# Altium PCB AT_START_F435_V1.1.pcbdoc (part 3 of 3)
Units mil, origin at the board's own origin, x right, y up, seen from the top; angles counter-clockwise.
Board outline 6521.81 x 4041.5 mil, 2 copper layers (Top Layer, Bottom Layer); 158 components, 212 nets, 714 pads, 868 vias.
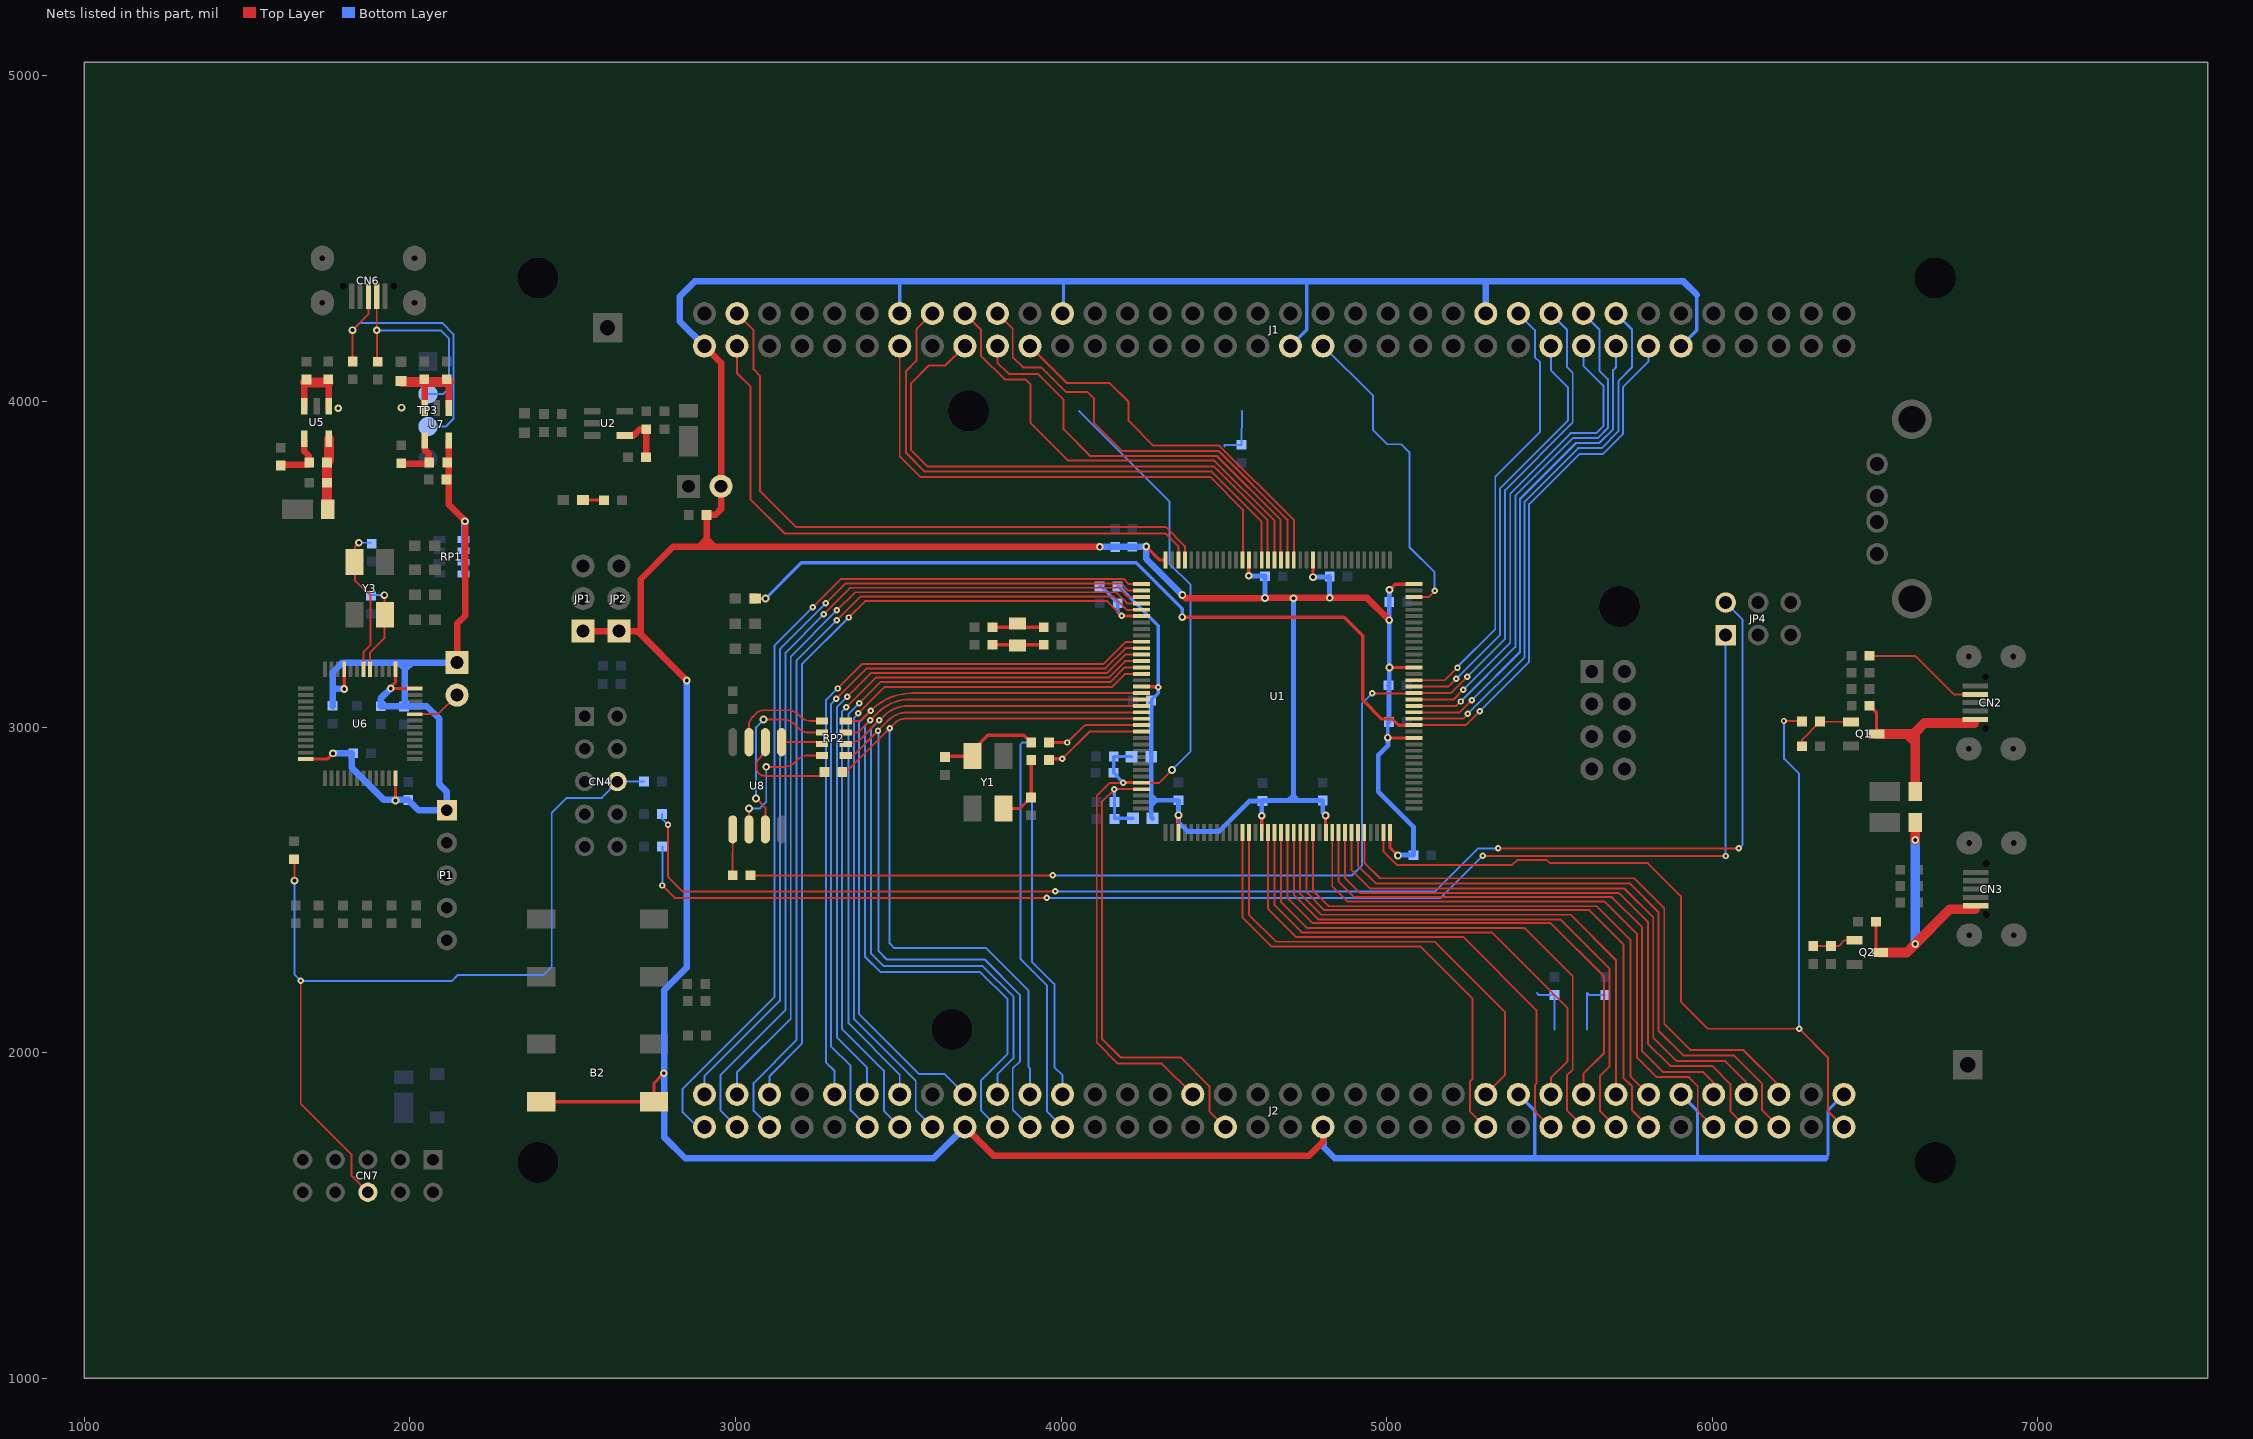
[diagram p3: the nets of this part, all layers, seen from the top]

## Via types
v1: diameter 19.69, hole 7.87, Top Layer to Bottom Layer, tented both sides, 787 vias
v2: diameter 23.62, hole 11.81, Top Layer to Bottom Layer, tented both sides, 53 vias
v3: diameter 24, hole 12, Top Layer to Bottom Layer, tented both sides, 17 vias
v4: diameter 35.43, hole 19.69, Top Layer to Bottom Layer, tented both sides, 11 vias

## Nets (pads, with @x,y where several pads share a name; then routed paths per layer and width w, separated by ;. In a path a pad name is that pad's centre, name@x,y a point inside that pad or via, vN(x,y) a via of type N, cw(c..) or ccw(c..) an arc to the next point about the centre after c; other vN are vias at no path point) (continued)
PD15: J1.14 LED4.2 U1.86 | length 4029.4
  Top Layer w6: U1.86@5084,3005.78 5243.09,3005.76 v1(5285.64,3048.36) ; J1.14@5804.59,4145.06 J1.14@5804.59,4170.06
  Top Layer w10: LED4.2@3060.29,3394.86 v3@3092.49,3394.66 ; v2(4372.18,3337.49) 4869.39,3337.47 4926.59,3280.36 4926.59,3083.36 4985.59,3024.26 5017.99,3024.26 5036.49,3005.76 U1.86@5084,3005.78
  Bottom Layer w6: v1(5285.64,3048.36) 5437.69,3200.36 5437.69,3684.36 5591.69,3838.36 5663.69,3838.36 5726.19,3900.86 5726.19,4044.86 5804.59,4123.27 J1.14@5804.59,4170.06
  Bottom Layer w10: v3(3092.47,3394.62) 3202.41,3504.56 4230.69,3504.56 4372.19,3363.07 v2(4372.18,3337.49)
PE0: J1.69 U1.141 | length 1992.3
  Top Layer w6: J1.69@3004.59,4269.56 3055.69,4218.97 3055.69,4098.27 3075.89,4078.07 3075.89,3724.16 3185.69,3614.36 4321.59,3614.36 4380.19,3555.76 U1.141@4380.19,3512.57
PE1: J1.70 U1.142 | length 1904
  Top Layer w6: J1.70@3004.59,4169.56 3004.59,4087.36 3045.69,4046.26 3045.69,3700.26 3151.69,3594.36 4321.69,3594.36 4360.49,3555.57 U1.142@4360.49,3512.57
PE2: J2.1 U1.1 | length 2855.2
  Top Layer w6: v1(3237.64,3368.36) 3324.19,3454.86 4192.49,3454.86 4208.59,3438.86 U1.1@4247.29,3438.86
  Bottom Layer w6: J2.1@2904.61,1771.46 2882.59,1771.46 2837.69,1816.37 2837.69,1888.37 3119.29,2169.97 3119.29,3250.07 v1(3237.64,3368.36)
PE3: J2.2 U1.2 | length 2667.5
  Top Layer w6: v1(3277.64,3380.36) 3338.69,3441.47 4184.59,3441.47 4206.99,3419.16 U1.2@4247.29,3419.16
  Bottom Layer w6: J2.2@2904.59,1871.57 2904.59,1927.07 3136.59,2159.07 3136.59,3239.36 v1(3277.64,3380.36)
PE4: J2.3 U1.3 | length 2748.8
  Top Layer w6: v1(3271.64,3346.36) 3352.99,3427.76 4176.79,3427.76 4204.99,3399.47 U1.3@4247.29,3399.47
  Bottom Layer w6: J2.3@3004.61,1771.46 2953.69,1822.46 2953.69,1930.96 3153.69,2130.97 3153.69,3228.36 v1(3271.64,3346.36)
PE5: J2.4 U1.4 | length 2586.9
  Top Layer w6: v1(3311.64,3358.36) 3367.19,3413.97 4168.89,3413.97 4203.09,3379.76 U1.4@4247.29,3379.76
  Bottom Layer w6: J2.4@3004.61,1871.46 3004.59,1938.77 3169.69,2103.86 3169.69,3216.36 v1(3311.64,3358.36)
PE6: J2.5 U1.5 | length 2665.3
  Top Layer w6: v1(3311.64,3328.36) 3383.39,3400.16 4161.79,3400.16 4201.89,3360.07 U1.5@4247.29,3360.07
  Bottom Layer w6: J2.5@3104.59,1771.57 3055.39,1820.77 3055.39,1906.46 3187.69,2038.77 3187.69,3204.36 v1(3311.64,3328.36)
PE7: J2.58 U1.58 | length 1655.4
  Top Layer w6: U1.58@4734.59,2676.05 4734.59,2487.36 4798.69,2423.36 5565.19,2423.36 5704.59,2283.97 J2.58@5704.61,1871.46
PE8: J2.59 U1.59 | length 1816.5
  Top Layer w6: U1.59@4754.19,2676.07 4754.19,2491.76 4808.69,2437.36 5622.59,2437.36 5727.19,2332.76 5727.19,1922.57 5753.69,1896.07 5753.69,1822.46 J2.59@5804.61,1771.46
PE9: J2.60 U1.60 | length 1714.1
  Top Layer w6: U1.60@4773.89,2676.07 4773.89,2497.07 4821.69,2449.36 5645.49,2449.36 5748.39,2346.47 5748.39,1927.66 J2.60@5804.61,1871.46
PE10: J2.63 U1.63 | length 1910
  Top Layer w6: U1.63@4833.01,2676.05 4832.99,2511.07 4879.69,2464.36 5668.89,2464.36 5768.49,2364.76 5768.49,1985.57 5829.69,1924.37 5928.39,1924.37 5955.69,1897.07 5955.69,1820.46 J2.63@6004.61,1771.46
PE11: J2.64 U1.64 | length 1817.7
  Top Layer w6: U1.64@4852.7,2676.05 4852.69,2525.26 4900.69,2477.36 5692.19,2477.36 5785.09,2384.47 5785.09,2003.46 5848.19,1940.37 5971.69,1940.37 6004.59,1907.37 J2.64@6004.61,1871.46
PE12: J2.65 U1.65 | length 1956.9
  Top Layer w6: U1.65@4872.29,2676.07 4872.29,2535.66 4917.69,2490.36 5713.49,2490.36 5802.39,2401.47 5802.39,2027.46 5870.49,1959.37 5999.69,1959.37 6055.69,1903.37 6055.69,1820.46 J2.65@6104.61,1771.46
PE13: J2.66 U1.66 | length 1851.3
  Top Layer w6: U1.66@4891.99,2676.07 4891.99,2560.97 4949.69,2503.36 5730.69,2503.36 5818.99,2415.07 5818.99,2045.57 5890.19,1974.37 6038.59,1974.37 6104.59,1908.37 J2.66@6104.61,1871.46
PE14: J2.67 U1.67 | length 1988.1
  Top Layer w6: U1.67@4911.75,2676.05 4911.69,2574.26 4966.69,2519.36 5746.99,2519.36 5835.09,2431.26 5835.09,2067.26 5911.99,1990.37 6067.19,1990.37 6153.69,1903.77 6153.69,1822.46 J2.67@6204.61,1771.46
PE15: J2.68 U1.68 | length 1884.7
  Top Layer w6: U1.68@4931.44,2676.05 4931.39,2583.57 4979.69,2535.36 5760.59,2535.36 5852.79,2443.16 5852.79,2088.16 5933.59,2007.37 6096.19,2007.37 6204.59,1898.96 J2.68@6204.61,1871.46
PF0: J2.10 U1.10 | length 2266
  Top Layer w6: v1@3313.69,3118.36 3388.99,3193.66 4130.99,3193.66 4198.99,3261.66 U1.10@4247.29,3261.66
  Bottom Layer w6: J2.10@3304.69,1871.46 3304.69,1943.37 3277.69,1970.27 3277.69,3082.36 v1@3313.69,3118.36
  other v1: 3313.64,3118.36
PF1: J2.11 U1.11 | length 2370.2
  Top Layer w6: v1@3309.69,3086.36 3403.19,3179.86 4136.19,3179.86 4198.29,3241.97 U1.11@4247.29,3241.97
  Bottom Layer w6: v1@3309.69,3086.36 3292.79,3069.47 3292.79,2019.77 3353.69,1958.87 3353.69,1822.46 J2.11@3404.59,1771.57
  other v1: 3309.64,3086.36
PF2: J2.12 U1.12 | length 2230
  Top Layer w6: v1@3343.69,3092.36 3417.39,3166.07 4141.39,3166.07 4197.59,3222.26 U1.12@4247.29,3222.26
  Bottom Layer w6: v1@3343.69,3092.36 3311.69,3060.36 3311.69,2046.96 3404.59,1954.07 J2.12@3404.61,1871.46
  other v1: 3343.64,3092.36
PF3: J2.13 U1.13 | length 2334.4
  Top Layer w6: v1@3339.69,3060.36 3431.19,3151.97 4145.99,3151.97 4196.69,3202.66 U1.13@4247.29,3202.66
  Bottom Layer w6: v1@3339.69,3060.36 3326.69,3047.36 3326.69,2073.36 3455.69,1944.27 3455.69,1820.57 J2.13@3504.59,1771.57
  other v1: 3339.64,3060.36
PF4: J2.14 U1.14 | length 2192.5
  Top Layer w6: v1@3379.69,3072.36 3445.09,3137.76 4150.99,3137.76 4196.19,3182.97 U1.14@4247.29,3182.97
  Bottom Layer w6: v1@3379.69,3072.36 3347.69,3040.36 3347.69,2089.36 3504.59,1932.46 J2.14@3504.59,1871.57
  other v1: 3379.64,3072.36
PF5: J2.15 U1.15 | length 2295.9
  Top Layer w6: v1(3377.64,3042.36) 3458.79,3123.57 4156.89,3123.57 4196.59,3163.26 U1.15@4247.29,3163.26
  Bottom Layer w6: v1(3377.64,3042.36) 3363.69,3027.57 3363.69,2103.36 3553.69,1913.37 3553.69,1822.46 J2.15@3604.61,1771.46
PF6: J2.18 RP2.4 U1.18 | length 2309.7
  Top Layer w6: RP2.4@3338.72,3018.67 cw(c3338.92,3018.47) 3338.92,3018.75 3375.79,3018.76 ; 3375.75,3018.75 ccw(c3375.75,3038.73) 3389.88,3024.6 v1(3415.64,3050.36) cw(c3545.62,2920.37) 3545.62,3104.19 ; 3545.59,3104.16 U1.18@4247.29,3104.16
  Bottom Layer w6: v1(3415.64,3050.36) 3379.69,3014.36 3379.69,2117.66 3562.89,1934.46 3641.69,1934.46 J2.18@3704.59,1871.57
PF7: J2.19 RP2.3 U1.19 | length 2615.1
  Top Layer w6: RP2.3@3338.72,2983.24 cw(c3338.85,2983.11) RP2.3@3338.85,2983.29 ; RP2.3@3338.89,2983.26 3371.39,2983.26 ; 3371.42,2983.29 ccw(c3371.42,2995.73) 3380.21,2986.93 v1(3413.64,3020.36) 3437.45,3044.17 cw(c3534.86,2946.76) 3534.86,3084.51 ; 3534.89,3084.57 U1.19@4247.29,3084.57
  Bottom Layer w6: v1@3413.69,3020.36 3397.69,3004.36 3397.69,2295.07 3445.49,2247.26 3751.59,2247.26 3835.59,2163.36 3835.59,1995.96 3753.69,1914.07 3753.69,1822.46 J2.19@3804.59,1771.57
PF8: J2.20 RP2.2 U1.20 | length 2489.2
  Top Layer w6: RP2.2@3338.72,2947.8 ccw(c3338.72,3021.09) 3390.55,2969.26 v1(3441.64,3020.36) 3454.97,3033.68 cw(c3530.2,2958.45) 3530.2,3064.85 3548.95,3064.85 cw(c3548.95,3064.77) 3549,3064.82 ; 3548.99,3064.86 U1.20@4247.29,3064.86
  Bottom Layer w6: v1(3441.64,3020.36) 3415.69,2994.36 3415.69,2305.47 3455.39,2265.76 3759.49,2265.76 3854.09,2171.26 3854.09,1983.37 3804.59,1933.87 J2.20@3804.61,1871.46
PF9: J2.21 RP2.1 U1.21 | length 2564.8
  Top Layer w6: RP2.1@3338.72,2912.37 3361.69,2912.36 v1@3437.69,2988.36 ; v1(3437.64,2988.36) 3471.06,3021.78 cw(c3527.47,2965.37) 3527.47,3045.14 ; 3527.49,3045.16 U1.21@4247.29,3045.16
  Bottom Layer w6: v1(3437.64,2988.36) 3439.69,2986.26 3439.69,2311.36 3465.19,2285.86 3764.99,2285.86 3874.19,2176.76 3874.19,1973.87 3851.69,1951.37 3851.69,1824.46 J2.21@3904.61,1771.46
PF10: J2.22 R21.1 U1.22 | length 2453.8
  Top Layer w6: R21.1@3328.05,2861.51 3338.89,2861.47 v1@3473.69,2996.36 ; v1(3473.64,2996.36) 3489.99,3012.71 cw(c3520.74,2981.95) 3520.75,3025.45 3543.87,3025.45 ; 3543.89,3025.47 U1.22@4247.29,3025.47
  Bottom Layer w6: v1@3473.69,2996.36 3473.69,2335.36 3488.09,2320.97 3769.79,2320.97 3899.79,2190.97 3899.79,1956.16 3904.89,1950.96 J2.22@3904.61,1871.46
PF11: J2.49 U1.49 | length 1489
  Top Layer w6: U1.49@4557.42,2676.05 4557.39,2414.57 4645.69,2326.36 5103.69,2326.36 5263.69,2166.36 5263.69,1918.37 5255.69,1910.37 5255.69,1820.46 J2.49@5304.61,1771.46
PF12: J2.50 U1.50 | length 1440.8
  Top Layer w6: U1.50@4577.11,2676.05 4577.09,2423.86 4660.59,2340.36 5147.79,2340.36 5364.29,2123.86 5364.29,1931.16 J2.50@5304.61,1871.46
PF13: J2.53 U1.53 | length 1569
  Top Layer w6: U1.53@4636.09,2676.07 4636.09,2440.36 4721.19,2355.36 5235.19,2355.36 5459.99,2130.57 5459.99,1904.66 5455.69,1900.37 5455.69,1820.46 J2.53@5504.61,1771.46
PF14: J2.54 U1.54 | length 1540.7
  Top Layer w6: U1.54@4655.85,2676.05 4655.79,2452.16 4738.69,2369.36 5322.79,2369.36 5555.69,2136.36 5555.69,1973.77 5504.59,1922.66 J2.54@5504.61,1871.46
PF15: J2.55 U1.55 | length 1695.3
  Top Layer w6: U1.55@4675.53,2676.05 4675.49,2463.26 4756.49,2382.36 5423.89,2382.36 5571.69,2234.57 5571.69,1947.66 5553.69,1929.66 5553.69,1822.46 J2.55@5604.61,1771.46
PG0: J2.56 U1.56 | length 1662.1
  Top Layer w6: U1.56@4695.22,2676.05 4695.19,2474.86 4772.69,2397.36 5504.19,2397.36 5667.69,2233.86 5667.69,1997.57 5604.59,1934.46 J2.56@5604.61,1871.46
PG1: J2.57 U1.57 | length 1774.5
  Top Layer w6: U1.57@4714.9,2676.05 4714.89,2484.07 4789.69,2409.36 5533.49,2409.36 5684.99,2257.86 5684.99,1957.66 5655.69,1928.37 5655.69,1820.46 J2.57@5704.61,1771.46
PG2: J1.15 U1.87 | length 1672.8
  Top Layer w6: U1.87@5084,3025.47 5234.69,3025.47 v1@5249.69,3040.36
  Bottom Layer w6: v1@5249.69,3040.36 5423.69,3214.36 5423.69,3692.36 5588.09,3856.76 5660.09,3856.76 5711.69,3908.36 5711.69,4062.36 5753.69,4104.36 5753.69,4220.97 J1.15@5704.59,4270.06
  other v1: 5249.64,3040.36
PG3: J1.16 U1.88 | length 1506.4
  Top Layer w6: U1.88@5084,3045.16 5224.39,3045.16 v1(5261.64,3082.36)
  Bottom Layer w6: v1(5261.64,3082.36) 5409.69,3230.36 5409.69,3700.36 5581.69,3872.36 5653.69,3872.36 5695.69,3914.36 5695.69,4096.47 5704.59,4105.36 J1.16@5704.59,4170.06
PG4: J1.17 U1.89 | length 1603.8
  Top Layer w6: U1.89@5083.99,3064.86 5214.09,3064.86 v1(5227.64,3078.36)
  Bottom Layer w6: v1(5227.64,3078.36) 5395.69,3246.36 5395.69,3710.36 5573.69,3888.36 5649.69,3888.36 5679.69,3918.36 5679.69,4068.36 5653.69,4094.36 5653.69,4220.97 J1.17@5604.59,4270.06
PG5: J1.18 U1.90 | length 1469.3
  Top Layer w6: U1.90@5084,3084.53 5205.79,3084.47 v1(5235.64,3114.36)
  Bottom Layer w6: v1(5235.64,3114.36) 5379.69,3258.36 5379.69,3716.97 5565.09,3902.36 5643.69,3902.36 5665.69,3924.36 5665.69,4048.36 5604.59,4109.36 J1.18@5604.59,4170.06
PG6: J1.19 R22.1 U1.91 | length 4023
  Top Layer w6: R22.1@3046.29,2544.37 v1@3974.69,2544.36 ; v1(4955.7,3103.45) 5083.29,3103.47 U1.91@5084,3104.2 5197.49,3104.16 v1(5247.64,3154.36)
  Bottom Layer w6: v1@3974.69,2544.36 4893.69,2544.36 4923.69,2574.36 4923.69,3071.45 v1(4955.7,3103.45) ; v1(5247.64,3154.36) 5363.69,3270.36 5363.69,3727.76 5571.69,3935.76 5571.69,4087.86 5553.69,4105.86 5553.69,4220.97 J1.19@5504.59,4270.06
  other v1: 3974.64,2544.36
PG7: J1.20 U1.92 | length 1326
  Top Layer w6: U1.92@5084,3123.89 5189.19,3123.86 v1@5213.69,3148.36
  Bottom Layer w6: v1@5213.69,3148.36 5347.69,3282.36 5347.69,3732.26 5557.69,3942.26 5557.69,4042.36 5504.59,4095.47 J1.20@5504.59,4170.06
  other v1: 5213.64,3148.36
PG8: J1.21 U1.93 | length 1370.4
  Top Layer w6: U1.93@5084,3143.57 5178.89,3143.57 v1(5217.64,3182.36)
  Bottom Layer w6: v1(5217.64,3182.36) 5217.64,3184.32 5333.69,3300.36 5333.69,3768.36 5471.69,3906.37 5471.69,4120.36 5455.69,4136.37 5455.69,4218.97 J1.21@5404.59,4270.06
PG9: J1.52 U1.124 | length 1212.9
  Top Layer w6: J1.52@3921.64,4153 J1.52@3904.61,4170.04 4018.29,4056.36 4149.59,4056.36 4207.69,3998.26 4207.69,3940.36 4283.69,3864.36 4486.59,3864.36 4714.89,3636.07 U1.124@4714.9,3512.68
PG10: J1.53 U1.125 | length 1371.6
  Top Layer w6: J1.53@3804.59,4270.06 3851.69,4222.97 3851.69,4136.36 3883.69,4104.36 3939.39,4104.36 4015.39,4028.36 4081.59,4028.36 4101.69,4008.36 4101.69,3933.57 4186.79,3848.36 4483.59,3848.36 4695.19,3636.76 U1.125@4695.22,3512.68
PG11: J1.54 U1.126 | length 1297.9
  Top Layer w6: J1.54@3804.59,4170.06 3804.59,4119.06 3839.29,4084.36 3927.89,4084.36 4007.69,4004.57 4007.69,3914.36 4089.69,3832.36 4478.69,3832.36 4674.69,3636.47 4674.69,3592.36 4674.69,3513.57 U1.126@4675.53,3512.68
PG12: J1.55 U1.127 | length 1451.3
  Top Layer w6: J1.55@3704.59,4270.06 3753.69,4220.97 3753.69,4140.36 3826.49,4067.57 3890.29,4067.57 3905.69,4052.16 3905.69,3935.16 4022.49,3818.36 4470.69,3818.36 4655.79,3633.16 U1.127@4655.85,3512.68
PG13: J1.56 U1.128 | length 1724.7
  Top Layer w6: J1.56@3704.59,4170.06 3644.89,4110.36 3593.69,4110.36 3539.69,4056.37 3539.69,3850.36 3589.7,3800.35 4468.73,3800.35 4634.64,3634.44 4634.64,3585.36 ; 4634.69,3585.36 4634.69,3514.16 U1.128@4636.09,3512.66
PG14: J1.57 U1.129 | length 1759.8
  Top Layer w6: J1.57@3604.59,4270.06 3555.69,4221.06 3555.69,4124.36 3523.69,4092.36 3523.69,3842.36 3581.69,3784.36 4463.09,3784.36 4615.59,3631.86 4615.59,3608.36 4615.59,3513.36 U1.129@4616.39,3512.66
PG15: J1.60 U1.132 | length 1616
  Top Layer w6: J1.60@3504.59,4170.06 3504.59,3831.37 3567.69,3768.36 4457.69,3768.36 4558.64,3667.41 4558.64,3595.36 ; U1.132@4557.42,3512.68 4558.69,3513.86 4558.69,3595.36
PH0/HEXT_IN: R1.2 U1.23 | length 430.5
  Top Layer w6: R1.2@3963.19,2952.36 v1(4019.64,2952.36) 4019.69,2952.36 4073.09,3005.76 U1.23@4247.29,3005.76
  Top Layer w10: R1.2@3963.14,2952.35 v1@4019.69,2952.36
  Bottom Layer w6: 3954.89,2952.36 v1@4019.69,2952.36 ; v1(4019.64,2952.36) v1@4021.65,2954.36
PH0_E: J2.23 | length 1265.6
  Bottom Layer w6: 3910.49,2952.36 3881.49,2952.36 3875.79,2946.66 3875.79,2287.26 3956.69,2206.36 3956.69,1819.46 J2.23@4004.61,1771.46
PH1/HEXT_OUT: R3.2 U1.24 | length 371.8
  Top Layer w6: v1@4003.69,2902.36 4087.39,2986.07 U1.24@4247.29,2986.07
  Top Layer w10: R3.2@3963.14,2898.35 3967.19,2902.36 v1@4003.69,2902.36
  Bottom Layer w6: 3954.89,2896.36 3960.89,2902.36 v1@4003.69,2902.36
  other v1: 4003.64,2902.36
PH1_E: J2.24 | length 1063.9
  Bottom Layer w6: 3910.49,2896.36 3910.49,2279.47 3979.79,2210.16 3979.79,1955.07 4004.59,1930.27 J2.24@4004.61,1871.46
PH2: J1.34 U1.106 | length 992.9
  Top Layer w6: U1.106@5084,3399.49 5130.79,3399.47 5147.59,3416.26 v1(5147.57,3418.26)
  Bottom Layer w6: J1.34@4804.59,4170.06 4805.99,4170.06 4957.69,4018.36 4957.69,3912.76 5001.89,3868.57 5045.59,3868.57 5069.69,3844.47 5069.69,3552.86 5147.59,3474.97 v1(5147.57,3418.26)
PH3: J2.71 R32.1 U1.71 | length 3141.6
  Top Layer w6: U1.71@4990.49,2676.05 4990.49,2617.47 5031.29,2576.66 5385.99,2576.66 5400.59,2591.26 5492.39,2591.26 5501.89,2581.76 5802.19,2581.76 5903.69,2480.26 5903.69,2155.47 5985.99,2073.16 6266.79,2073.16 6355.69,1984.27 6355.69,1820.46 J2.71@6404.61,1771.46 ; v1(6220.44,3018.36) 6274.19,3018.36 R32.1@6276,3016.56
  Bottom Layer w6: v1@6220.83,3017.96 6220.83,2902.12 6266.81,2856.14 v1(6266.81,2073.14)
Q1_1: Q1.1 R32.2 R33.1 | length 193.9
  Top Layer w6: R33.1@6276,2940.56 6275.99,2961.57 R32.2@6331,3016.56 Q1.1@6426.12,3015.97
QSPI1_IO0: RP2.7 U8.5 | length 126.6
  Top Layer w6: U8.5@3141.59,2953.36 3260.39,2953.36 RP2.7@3265.89,2947.8
QSPI1_IO1: RP2.8 U8.2 | length 416.2
  Top Layer w6: U8.2@3041.59,2685.66 3041.59,2750.07 v3@3042.39,2750.07 ; v3(3094.44,2877.7) 3150.84,2877.7 ccw(c3150.84,2919.4) 3180.33,2889.91 3189.41,2898.99 cw(c3221.7,2866.71) 3221.7,2912.37 RP2.8@3265.89,2912.37
  Bottom Layer w6: v3@3041.59,2750.07 3074.79,2750.07 3094.49,2769.76 v3@3094.49,2877.66
  other v3: 3041.55,2750.03
QSPI1_IO2: RP2.6 U8.3 | length 550.4
  Top Layer w6: v3(3063.31,2780.78) 3091.59,2752.57 U8.3@3091.59,2685.66 ; v3(3086.17,3022.68) 3146,3022.68 cw(c3146,2970.23) 3183.09,3007.32 3195.7,2994.71 ccw(c3223.27,3022.29) 3223.27,2983.29 ; 3223.29,2983.26 RP2.6@3265.79,2983.26 ; RP2.6@3265.76,2983.29 cw(c3265.76,2983.11) RP2.6@3265.89,2983.24
  Bottom Layer w6: v3(3063.31,2780.78) 3063.31,2999.83 v3(3086.17,3022.68)
QSPI1_IO3: RP2.5 U8.7 | length 310.8
  Top Layer w6: 3041.55,3004.66 cw(c3078.19,3004.66) 3052.28,3030.57 3064.25,3042.53 cw(c3085.77,3021.01) 3085.77,3051.45 3161.38,3051.45 cw(c3161.38,3005.71) 3193.72,3038.05 3201.05,3030.73 ccw(c3229.97,3059.65) 3229.97,3018.75 ; U8.7@3041.59,2953.36 3041.59,3004.66 ; 3229.99,3018.76 3265.69,3018.76 cw(c3265.69,3018.47) RP2.5@3265.89,3018.67
QSPI1_NSS: R22.2 U8.1 | length 141.3
  Top Layer w6: R22.2@2991.29,2544.37 U8.1@2991.59,2685.66
QSPI1_SCK: R21.2 U8.6 | length 314.8
  Top Layer w6: U8.6@3091.55,2953.36 3091.55,2948.25 cw(c3027.43,2948.25) 3072.77,2902.91 ccw(c3091.79,2883.89) 3064.89,2883.89 3064.89,2874.15 ccw(c3088.92,2874.15) 3088.92,2850.12 3162.2,2850.12 ; 3162.19,2850.16 R21.2@3261.69,2850.16 ; R21.2@3261.66,2850.12 ccw(c3261.66,2861.51) R21.2@3273.05,2861.51
R10_2: LED1.1 R10.2 | length 64.5
  Top Layer w10: LED1.1@2531.68,3697.15 R10.2@2596.19,3696.36
R29_2: CN2.4 R29.2 | length 373.4
  Top Layer w6: R29.2@6483.09,3218.66 6623.49,3218.66 6741.99,3100.26 CN2.4@6807.49,3100.29
R36_1: Q2.1 R36.1 R37.2 | length 134.1
  Top Layer w6: R37.2@6310.53,2327.08 R36.1@6364.53,2327.08 6388.09,2327.07 6405.99,2344.97 Q2.1@6437.19,2344.97
R57_2: R57.2 | length 163
  Bottom Layer w6: 5461.69,2183.07 5467.89,2176.86 R57.2@5515.64,2176.85 5515.29,2070.36
R58_2: R59.2 | length 171.2
  Bottom Layer w6: 5615.29,2070.36 5615.69,2183.07 5621.89,2176.86 R59.2@5671.64,2176.85
R61_2: R61.2 | length 161.8
  Bottom Layer w6: 4501.59,3861.66 4501.59,3866.86 4554.69,3866.86 4555.29,3970.36
S$36943: 
S$36957: 
S$36960: 
S$36971: 
S$36989: 
S$36999: 
S$59049: 
S$59582: 
SWO: CN4.6 CN7.6 R23.1 R52.1 | length 2694.2
  Top Layer w6: v2@1645.69,2528.07 R52.1@1645.69,2585.97 ; v1(1664.64,2220.36) 1664.64,1842.36 1820.64,1686.35 1820.64,1621.23 CN7.6@1870.89,1570.96
  Bottom Layer w6: v2(1645.66,2528.01) 1645.66,2239.34 v1(1664.64,2220.36) ; v1(1664.64,2220.36) 2129.69,2220.36 2147.69,2238.36 2410.69,2238.36 2435.69,2263.36 2435.69,2736.36 2481.69,2782.36 2589.33,2782.35 CN4.6@2636.53,2832.54 ; CN4.6@2636.59,2832.57 2718.79,2832.57 R23.1@2718.99,2832.76
U2_4: R15.1 R16.1 U2.4 | length 160.8
  Top Layer w20: U2.4@2659.69,3895.36 2686.59,3895.36 2706.19,3914.86 2725.69,3914.86 2725.69,3828.86 R15.1@2725.14,3828.35
U5_4: R50.1 R51.1 U5.4 | length 163.5
  Top Layer w20: R51.1@1604.49,3805.07 1689.49,3805.07 1689.49,3833.07 1675.69,3846.76 U5.4@1675.69,3877.86
U6_44: J9.2 U6.44 | length 154.6
  Top Layer w6: U6.44@2014.69,3039.26 2086.09,3039.26 J9.2@2144.89,3098.07
U7_1: C15.1 C16.1 C18.1 C19.1 F2.2 U5.1 U5.3 U7.1 U7.3 | length 539.5
  Top Layer w20: U5.3@1675.69,3977.86 1675.69,4056.86 C19.1@1676.69,4057.86 ; U5.1@1750.69,3977.86 C18.1@1750.69,4057.86 ; U7.3@2044.86,3979.91 C15.1@2044.89,4058.07 ; U7.1@2119.86,3979.91 C16.1@2119.89,4059.86
  Top Layer w30: C19.1@1676.69,4057.86 C18.1@1750.69,4057.86 ; F2.2@1973.09,4059.97 2119.79,4059.97 C16.1@2119.89,4059.86
  other v2: 1779.86,3979.01 1973.86,3981.01
U7_4: R43.1 R49.1 U7.4 | length 163.4
  Top Layer w20: R49.1@1972.49,3808.07 2058.49,3808.07 2058.49,3838.97 2044.89,3852.57 U7.4@2044.86,3879.91
USART1_RX: JP4.2 R24.2 | length 4345
  Top Layer w6: v1(2792.64,2699.36) 2792.64,2539.35 2836.64,2495.36 v1(3981.64,2495.36) ; v1@5342.19,2627.07 v1@6082.19,2627.07
  Bottom Layer w6: R24.2@2774.39,2732.66 2774.39,2717.66 v1@2792.69,2699.36 ; v1(3981.64,2495.36) 5149.79,2495.36 5281.49,2627.07 v1@5342.19,2627.07 ; JP4.2@6041.19,3382.36 6093.59,3329.97 6093.59,2638.47 v1@6082.19,2627.07
  other v1: 5342.24,2627.05 6082.14,2627.11
USART1_TX: JP4.1 R25.2 | length 4133
  Top Layer w6: v1(2775.3,2513.24) 2813.19,2475.36 v1(3956.64,2475.36) ; v1(5294.99,2604.2) 5295.33,2603.86 v1(6041.17,2603.86)
  Bottom Layer w6: R25.2@2775.19,2632.66 2775.19,2513.36 v1@2775.29,2513.26 ; v1(3956.64,2475.36) 5166.14,2475.36 v1(5294.99,2604.2) ; v1(6041.17,2603.86) JP4.1@6041.19,3282.36
USBM: CN6.2 R12.1 TP3.2 | length 659.2
  Top Layer w6: CN6.2@1898.23,4322.59 1898.09,4322.47 v2(1898.09,4218.56) 1898.19,4218.56 1898.19,4124.97 R12.1@1901.09,4122.06
  Bottom Layer w6: v2(1898.09,4218.56) 2094.89,4218.56 2120.44,4193.02 2120.44,4041.01 2102.44,4023.02 TP3.2@2055.44,4023.01
USBP: CN6.3 R11.1 TP3.3 | length 900.9
  Top Layer w6: R11.1@1824.09,4123.06 1824.09,4219.27 1872.59,4267.77 CN6.3@1872.64,4322.59
  Bottom Layer w6: v2(1823.86,4219.02) 1845.86,4241.02 2099.44,4241.02 2133.44,4207.02 2133.44,3946.01 2110.44,3923.01 TP3.3@2055.44,3923.01
VBAT: C35.1 J2.6 R9.1 U1.6 | length 2808.9
  Top Layer w6: v1(3347.64,3336.36) 3397.99,3386.76 4141.19,3386.76 4187.49,3340.47 U1.6@4247.29,3340.47
  Top Layer w10: v1(4186.64,3341.36) U1.6@4247.29,3340.47
  Bottom Layer w6: J2.6@3104.61,1871.46 3104.59,1928.07 3203.69,2027.16 3203.69,3192.36 v1(3347.64,3336.36) ; R9.1@4118.13,3431.66 4122.89,3431.66 C35.1@4174.14,3380.35 ; C35.1@4174.19,3380.36 4174.19,3353.86 v1@4186.69,3341.36
  Bottom Layer w10: R9.1@4118.13,3431.66 4122.89,3431.66 C35.1@4174.14,3380.35 4174.09,3353.86 v1(4186.64,3341.36)
VBUS1: CN2.1 D2.2 Q1.3 R34.2 | length 625.2
  Top Layer w10: R34.2@6483.59,3065.26 6504.89,3043.97 Q1.3@6504.86,2978.57
  Top Layer w30: Q1.3@6504.86,2978.57 6623.79,2978.57 ; 6596.31,2978.56 6623.49,2954.92 ; D2.2@6623.75,2801.65 6623.79,2983.57 6652.69,3012.47 6804.69,3012.47
VBUS2: CN3.1 D6.2 Q2.3 R35.2 | length 818.9
  Top Layer w10: R35.2@6502.89,2401.76 6502.89,2320.57 Q2.3@6515.86,2307.57
  Top Layer w30: Q2.3@6515.86,2307.57 6597.79,2307.57 v3(6623.76,2333.59) 6730.49,2440.36 6807.49,2440.36 ; v3@6623.79,2653.16 D6.2@6623.75,2706.31
  Bottom Layer w30: v3(6623.76,2333.59) v3(6623.76,2653.11)
VCC: C8.1 C9.1 C10.1 C11.1 C12.1 C14.1 J9.1 P1.1 R43.2 RP1.1 RP1.2 RP1.3 RP1.4 U6.1 U6.9 U6.24 U6.36 U6.48 U7.5 | length 2944.6
  Top Layer w10: U6.24@1679.99,2901.47 1745.89,2901.47 v2@1763.49,2918.97 ; v2(1798.09,3116.57) U6.9@1798.09,3177.07 ; U6.36@1955.6,2842.36 1955.59,2774.26 v2(1955.86,2774.01) ; U6.1@1955.59,3177.07 1955.59,3136.76 1941.09,3122.26 v2(1941.09,3118.57) 1975.19,3118.57 1975.79,3117.97 U6.48@2014.66,3117.97
  Top Layer w20: U7.5@2119.86,3879.91 2119.89,3682.76 2169.89,3632.76 2169.89,3342.07 2144.89,3317.07 J9.1@2144.89,3198.07
  Bottom Layer w20: 1762.86,3118.02 1796.64,3118.02 v2(1798.09,3116.57) ; C12.1@1762.89,3063.97 1762.89,3168.07 1792.89,3198.07 1964.39,3198.07 1983.89,3178.57 ; v2@1763.49,2918.97 1820.89,2918.97 1820.89,2875.47 1920.29,2776.07 C11.1@1995.09,2776.07 2026.59,2744.57 P1.1@2113.59,2744.57 2113.59,2800.36 2090.49,2823.47 2090.49,3025.36 2051.89,3063.97 1909.89,3063.97 1909.89,3087.36 v2(1941.09,3118.57) ; 1965.59,3198.07 J9.1@2144.89,3198.07 ; C9.1@1983.89,3063.97 1983.89,3178.57 ; 2008.58,3198.07 1983.89,3178.57 ; RP1.4@2166.49,3470.57 2166.49,3632.07 v2@2169.49,3632.07
  other v2: 1763.44,2919.01 2169.44,3632.01
VCC3.5V: C17.1 D5.2 R50.2 U5.5 | length 440.5
  Top Layer w20: D5.2@1747.89,3668.57 1747.89,3748.26 C17.1@1745.59,3750.57 R50.2@1745.59,3812.57 1745.59,3833.16 1751.09,3838.66 U5.5@1751.09,3885.56
  Top Layer w30: D5.2@1747.89,3668.57 1745.59,3670.86 C17.1@1745.59,3750.57 R50.2@1745.59,3812.57 1751.09,3818.07 U5.5@1751.09,3885.56
VDD: B2.1 B2.3 C23.1 C24.1 C25.1 C26.1 C27.1 C28.1 C29.1 C30.1 C31.1 C32.1 C33.1 C34.1 J1.12 J1.23 J1.36 J1.49 J1.59 J1.72 J2.17 J2.39 J2.52 J2.62 J2.72 JP1.1 JP2.1 JP3.2 L1.1 L2.1 R9.2 R17.2 U1.17 U1.39 U1.52 U1.62 U1.72 U1.84 U1.95 U1.108 U1.121 U1.131 U1.144 | length 19408.9
  Top Layer w6: U1.17@4247.29,3123.86 4248.89,3122.36 v1@4298.49,3122.36 ; v2@4261.69,3554.36 4303.29,3512.66 U1.144@4321.2,3512.68 ; v2(4576.64,3464.36) 4576.59,3512.26 U1.131@4577.11,3512.68 ; v2@4773.69,3460.36 4773.69,3512.36 U1.121@4773.89,3512.66 ; v2(4812.64,2728.36) 4813.29,2727.66 U1.62@4813.33,2676.05 ; v2@5003.69,2967.36 5004.59,2966.36 U1.84@5084,2966.41 ; v2@5008.69,3182.97 U1.95@5083.99,3182.97 ; v2@5008.69,3421.36 5026.09,3438.86 U1.108@5084,3438.86 ; U1.72@5010.09,2676.07 5010.09,2629.86 v2@5034.69,2605.36
  Top Layer w10: B2.3@2403.39,1848.77 B2.1@2749.91,1848.78 2749.89,1906.57 v2@2779.69,1936.37 ; U1.17@4247.29,3123.86 4296.99,3123.86 v1@4298.49,3122.36 ; v2(4261.64,3554.36) 4303.29,3512.66 U1.144@4321.2,3512.68 ; U1.39@4360.49,2676.07 v2(4360.52,2729.36) ; v2(4576.64,3464.36) U1.131@4577.11,3512.68 ; U1.52@4616.39,2676.07 v2(4616.46,2727.59) ; v2@4773.69,3460.36 U1.121@4773.89,3512.66 ; v2(4812.64,2728.36) U1.62@4813.33,2676.05 ; v2@5003.69,2967.36 U1.84@5084,2966.41 ; v2@5008.69,3182.97 U1.95@5083.99,3182.97 ; v2@5008.69,3421.36 5026.09,3438.86 U1.108@5084,3438.86 ; U1.72@5010.09,2676.07 5010.09,2629.86 v2@5034.69,2605.36
  Top Layer w20: JP1.1@2531.79,3294.57 2641.79,3294.57 2698.69,3294.57 v2(2850.51,3142.8) ; 2696.99,3294.36 2708.69,3284.57 2708.69,3453.66 2808.39,3553.36 2951.59,3553.36 ; 2889.7,3553.36 2911.19,3577.86 ; J1.72@2904.61,4170.04 2955.64,4119.01 JP3.2@2955.64,3739.35 ; JP3.2@2955.64,3739.35 2955.59,3669.36 2937.69,3651.36 2911.19,3651.36 2911.19,3577.86 ; J2.17@3704.61,1771.46 3793.71,1682.35 4760.64,1682.35 4804.61,1726.32 J2.39@4804.61,1771.46 ; v2@4118.69,3553.36 2935.69,3553.36 2911.19,3577.86 ; v2(4372.64,3405.36) 4381.8,3396.2 v2(4626.71,3396.2) 4627.11,3396.59 v2(4825.28,3396.59) 4939.89,3396.59 v2(5008.14,3328.36)
  Bottom Layer w6: R9.2@4178.29,3431.66 4298.49,3311.47 4298.49,3122.36 4298.49,3103.76 C25.1@4276.19,3081.36 ; v2(4576.64,3464.36) 4577.59,3463.36 C34.1@4626.19,3463.36 ; v2@4773.69,3460.36 4775.59,3462.36 C33.1@4825.14,3462.35 ; C32.1@5008.14,3384.35 5008.09,3420.86 v2@5008.69,3421.36 ; v2@5034.69,2605.36 5035.69,2606.36 C29.1@5082.19,2606.36
  Bottom Layer w10: J1.59@3504.61,4270.04 3504.61,4366.57 3506.8,4368.77 ; J1.49@4004.61,4270.04 4007.63,4273.06 4007.63,4368.89 ; R9.2@4173.13,3431.66 4178.29,3431.66 4211.29,3398.57 ; 4209.88,3400.02 4298.54,3311.36 v1(4298.54,3122.32) ; C25.1@4276.19,3081.36 4298.49,3103.76 v1@4298.49,3122.36 ; J1.36@4704.61,4170.04 4754.7,4220.13 4754.7,4368.77 ; v2@5003.69,2967.36 5003.69,3011.86 C30.1@5007.19,3015.36 ; J2.52@5404.61,1871.46 5454.64,1821.42 5454.64,1675.37 ; J2.62@5904.61,1871.46 5954.64,1821.42 5954.64,1675.37 ; J1.12@5904.61,4170.04 5952.64,4218.07 5952.64,4328.35 ; 6346.69,1675.37 6355.69,1684.37 6355.69,1822.46 J2.72@6404.61,1871.46
  Bottom Layer w15: C25.1@4276.19,3081.36 L2.1@4277,2908.36 4276.99,2723.36 L1.1@4281,2719.36 ; 4276.99,2760.36 4291.49,2774.86 ; 4276.99,2790.16 4291.49,2774.86 ; v2@4576.59,3463.36 4626.19,3463.36 4626.19,3396.66 v2(4626.71,3396.2) ; v2(4616.46,2727.59) 4616.49,2770.66 4618.69,2772.86 4579.09,2772.86 4485.69,2679.36 4388.69,2679.36 4360.49,2707.47 v2(4360.52,2729.36) 4360.69,2774.86 4291.49,2774.86 ; C27.1@4618.69,2773.86 4803.69,2773.86 4803.69,2737.36 v2@4812.69,2728.36 ; 4697.64,2774.55 4712.94,2789.05 ; 4714.13,2773.86 v2(4714.13,3395.36) ; 4714.25,2789.37 4728.75,2774.07 ; v2@4773.69,3460.36 4823.09,3460.36 C33.1@4825.14,3462.35 4825.09,3396.76 v2(4825.28,3396.59) ; v2@5003.69,2967.36 5003.69,2942.97 4974.19,2913.57 4974.19,2801.26 5082.19,2693.36 5082.19,2606.36 5035.59,2606.36 v2@5034.69,2605.36 ; C30.1@5007.19,3015.36 5007.19,3127.36 5006.19,3128.36 5008.09,3130.36 C32.1@5008.14,3384.35 v2@5008.69,3421.36
  Bottom Layer w20: v2(2850.51,3142.8) 2850.51,2261.22 2780.69,2191.4 2780.69,1740.37 2845.69,1675.37 3608.49,1675.37 J2.17@3704.61,1771.46 ; J1.72@2904.59,4170.06 2828.89,4245.77 2828.89,4322.66 2874.99,4368.77 5912.19,4368.77 5952.69,4328.36 ; v2(4118.64,3553.36) 4119.64,3554.35 v2(4261.64,3554.36) ; v2(4261.64,3554.36) 4261.59,3516.36 v2(4372.64,3405.36) ; J2.39@4804.61,1771.46 4806.64,1769.42 4806.64,1709.35 4840.63,1675.37 6346.69,1675.37 ; J1.23@5304.61,4270.04 5304.61,4368.77 5307.98,4368.77
  other v2: 2779.64,1936.36 5034.64,2605.36 5003.64,2967.36 5008.64,3182.93 5008.64,3421.36 4773.64,3460.36
VDDA: C36.1 C37.1 J2.33 L1.2 U1.33 | length 1641
  Top Layer w6: U1.33@4247.29,2808.97 4164.29,2808.97 4125.69,2770.36 4125.69,2042.27 4182.59,1985.37 4367.59,1985.37 4455.69,1897.27 4455.69,1820.46 J2.33@4504.61,1771.46
  Bottom Layer w6: v1@4163.69,2808.36 4164.09,2807.86 C37.1@4164.14,2769.35 C36.1@4164.14,2717.35
  Bottom Layer w10: v1@4163.69,2808.36 C37.1@4164.14,2769.35 C36.1@4164.14,2717.35 4166.19,2719.36 L1.2@4220.37,2719.36
  other v1: 4163.64,2808.36
VREF+: C38.1 C39.1 J2.32 L2.2 U1.32 | length 3013.5
  Top Layer w6: v1(4191.64,2829.36) 4246.59,2829.36 U1.32@4247.29,2828.57 ; v3(4341.06,2868.39) 4301.29,2828.57 U1.32@4247.29,2828.57 ; J2.32@4404.61,1871.46 4309.69,1966.37 4174.79,1966.37 4109.69,2031.46 4109.69,2788.36 4149.89,2828.57 U1.32@4247.29,2828.57
  Top Layer w10: v1(4191.64,2829.36) U1.32@4247.29,2828.57
  Bottom Layer w6: 4055.29,3970.36 4333.69,3691.97 4333.69,3500.36 4397.69,3436.36 4397.69,2924.97 v3(4341.06,2868.39) ; C38.1@4161.19,2859.36 4162.19,2860.36 4162.19,2909.36 L2.2@4216.29,2908.36
  Bottom Layer w10: v1(4191.64,2829.36) 4161.19,2859.36 4162.19,2860.36 4162.19,2909.36 L2.2@4216.37,2908.36
X1_1: C4.2 R6.1 X1.1 | length 159.8
  Top Layer w10: C4.2@3789.18,3252.78 3863.49,3252.76 X1.1@3866.28,3249.95 3869.09,3252.76 R6.1@3946.74,3252.78
X1_2: C3.2 R5.1 X1.2 | length 173.6
  Top Layer w10: C3.2@3789.18,3306.57 3866.29,3306.57 X1.2@3866.28,3317.87 3877.59,3306.57 R5.1@3946.79,3306.57
Y1_1: C1.2 R1.1 Y1.1 | length 396.8
  Top Layer w6: C1.2@3643.69,2907.86 3727.19,2907.86 Y1.1@3728.39,2909.07
  Top Layer w10: C1.2@3643.69,2907.86 3646.89,2911.07 3728.49,2911.07 3728.49,2928.16 3775.29,2974.97 3885.49,2974.97 R1.1@3908.14,2952.35
Y1_3: C2.2 R3.1 Y1.3 | length 213.9
  Top Layer w10: Y1.3@3822.93,2749.66 3873.89,2749.66 3908.09,2783.86 R3.1@3908.14,2898.35
Y3_1: C20.1 U6.5 Y3.1 | length 287.6
  Top Layer w6: U6.5@1876.89,3177.07 1876.89,3228.47 1921.69,3273.26 1921.69,3343.36 1921.49,3343.57 v2@1921.49,3405.07
  Bottom Layer w6: C20.1@1880.49,3405.07 v2@1921.49,3405.07
  other v2: 1921.44,3405.01
Y3_3: C21.2 U6.6 Y3.3 | length 459.6
  Top Layer w6: v2@1843.19,3565.97 1831.19,3554.07 1831.19,3508.66 1831.19,3451.26 1878.49,3403.97 1878.49,3251.26 1857.19,3230.07 U6.6@1857.19,3177.07
  Bottom Layer w6: v2@1843.19,3565.97 C21.2@1880.49,3565.97
  other v2: 1843.14,3566.01
pads on no net: CN2.MH1 CN2.MH2 CN3.MH1 CN3.MH2 CN6.4 CN6.MH1 CN6.MH2 J2.30 U1.30 U6.2 U6.3 U6.4 U6.14 U6.15 U6.16 U6.17 U6.18 U6.21 U6.22 U6.29 U6.38 U6.41 U6.42 U6.43 U6.45 U6.46

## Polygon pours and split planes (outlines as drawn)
GND on Bottom Layer (solid): 1503.07,4539.19 1503.07,1506.18 7016.71,1506.18 7017.49,1506.18 7017.49,4536.44 7017.49,4536.83 7006.07,4536.83
GND on Top Layer (solid): 1503.07,4539.19 1503.07,1506.18 7016.71,1506.18 7017.49,1506.18 7017.49,4536.44 7017.49,4536.83 7006.07,4536.83

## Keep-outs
Keep-Out Layer:
  lines w8 net S$36943: 2158.39,4536.6 cw(c2158.39,4457.86) 2237.13,4457.86 ; 2158.82,1505 ccw(c2158.82,1583.74) 2237.56,1583.74 ; 2276.39,1583.74 ccw(c2355.13,1583.74) 2355.13,1505 ; 2276.64,4457.84 cw(c2355.38,4457.84) 2355.38,4536.58
  lines w8 net S$36971: 2237.13,3408.87 ccw(c2238,3408.87) 2238,3408 ; 2276.29,3408 ccw(c2276.29,3408.35) 2276.65,3408.35
  lines w10: 1505,1583.74 ccw(c1583.74,1583.74) 1583.74,1505 ; 1505,4457.76 cw(c1583.74,4457.76) 1583.74,4536.5 ; 6938.07,1505 ccw(c6938.07,1583.74) 7016.81,1583.74 ; 6938.07,4536.5 cw(c6938.07,4457.76) 7016.81,4457.76

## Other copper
Top Layer:
  drawing of 766 lines, arcs and shapes, not listed
Bottom Layer:
  drawing of 519 lines, arcs and shapes, not listed

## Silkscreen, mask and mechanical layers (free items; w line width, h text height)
Top Overlay:
  region: 5636.49,3845.15 5598.49,3845.15 5618.49,3865.15 5638.49,3845.15
  region: 5498.13,3863.14 5536.13,3863.14 5516.13,3843.14 5496.13,3863.14
  lines w6: 1738.29,1808.99 1738.29,2107.99 ; 1828.52,1808.21 1828.52,2107.21 ; 1925.83,1811.14 1925.83,2111.14 ; 2012.12,1812.68 2012.12,2106.68
  lines w6 net S$59582: 5881.02,3610.29 6434.91,3610.73 6434.91,3455.63 5881.81,3455.17 ; 5881.42,3532.73 6434.91,3532.57 ; 5881.81,3455.19 5881.81,3610.29 ; 6034.91,3455.63 6036.91,3455.63 6036.91,3610.73 ; 6243.91,3455.63 6243.91,3610.73
  lines w8: 1818.43,1723.02 1818.43,1763.02 1918.43,1763.02 1918.43,1722.02 ; 2108.98,1777.02 2071.98,1740.02 2032.98,1779.02 2108.98,1779.02 ; 2435.62,3069.36 2435.62,2993.36 2474.62,3032.36 2437.62,3069.36
  lines w8 net S$59049: 2486.53,2878.97 2463.68,2878.97 2463.68,2779.68 2486.69,2779.68 2486.69,2780.88
  lines w10: 4228.13,3717.14 5643.83,3717.14 ; 4515.6,2363.13 4968.6,2363.13 ; 5113.84,2363.13 5673.84,2363.13
  text "143" at 2867.44,4421.62 h36
  text "133" at 3352.08,4421.62 h36
  text "123" at 3856.81,4421.56 h36
  text "113" at 4374.13,4421.65 h36
  text "103" at 4860.35,4421.65 h36
  text "93" at 5372.7,4421.66 h36 r3
  text "83" at 5877.67,4421.65 h36
  text "73" at 6372.55,4421.64 h36
  text "D8" at 6195.39,4324.61 h36 r45
  text "B12" at 6408.1,4323.95 h36 r45
  text "D7" at 3899.45,4323.25 h36 r45
  text "E0" at 3010.67,4322.49 h36 r45
  text "B8" at 3107.06,4321.52 h36 r45
  text "B3" at 3407.18,4321.84 h36 r45
  text "D1" at 4305.87,4321.86 h36 r45
  text "A9" at 5006.61,4321.6 h36 r45
  text "D12" at 5994.87,4321.81 h36 r45
  text "D10" at 6094.67,4322.5 h36 r45
  text "B14*" at 6298.96,4321.59 h36 r45
  text "B5" at 3308.54,4321.14 h36 r45
  text "A14" at 4596.68,4320.85 h36 r45
  text "A13" at 4794.43,4321.08 h36 r45
  text "D14" at 5799.64,4320.85 h36 r45
  text "D5" at 4111.44,4320.18 h36 r45
  text "D3" at 4207.39,4320.39 h36 r45
  text "A11*" at 4898.48,4320.33 h36 r45
  text "B7" at 3205.75,4318.1 h36 r45
  text "G10" at 3798.01,4317.55 h36 r45
  text "G8" at 5400.62,4317.9 h36 r45
  text "GND" at 4694.22,4316.52 h36 r45
  text "G2" at 5700.44,4317.15 h36 r45
  text "G12" at 3698.1,4316.1 h36 r45
  text "C7" at 5206.34,4315.63 h36 r45
  text "G6" at 5503.28,4316.27 h36 r45
  text "GND" at 2914.68,4315.15 h36 r45
  text "C9" at 5100.19,4315.33 h36 r45
  text "G4" at 5597.88,4315.4 h36 r45
  text "G14" at 3597.12,4313.68 h36 r45
  text "C12" at 4397.97,4313.73 h36 r45
  text "GND" at 5892.12,4314.43 h36 r45
  text "VDD" at 3997.94,4312.96 h36 r45
  text "C10" at 4500.14,4313.01 h36 r45
  text "VDD" at 5289.85,4312.93 h36 r45
  text "VDD" at 3493.62,4309.69 h36 r45
  text "GND" at 2560,4303.76 h36
  text "B6" at 3323.32,4035.33 h36 r45
  text "B9" at 3120.67,4031.8 h36 r45
  text "E1" at 3016.31,4028.92 h36 r45
  text "B4" at 3416.54,4029.12 h36 r45
  text "D6" at 4012.78,4028.92 h36 r45
  text "C8" at 5210.74,4026.48 h36 r45
  text "OTG1_HOST" at 6534,4025.66 h56
  text "G11" at 3810.61,4024.75 h36 r45
  text "D4" at 4218.1,4022.83 h36 r45
  text "G9" at 3904.97,4022.37 h36 r45
  text "D0" at 4419.38,4022.03 h36 r45
  text "G5" at 5611.64,4021.72 h36 r45
  text "G3" at 5714.34,4021.55 h36 r45
  text "G13" at 3687.34,4020.62 h36 r30
  text "D2" at 4319.78,4020.68 h36 r45
  text "H2" at 4813.22,4021.4 h36 r45
  text "C6" at 5318.27,4020.96 h36 r45
  text "G7" at 5513.47,4020.73 h36 r45
  text "A8" at 5113.58,4019.66 h36 r45
  text "D9" at 6211.89,4019.39 h36 r45
  text "C11" at 4514.08,4016.84 h36 r45
  text "A10" at 5009.5,4016.92 h36 r45
  text "G15" at 3508.61,4015.14 h36 r45
  text "D11" at 6112.11,4013.8 h36 r45
  text "A15" at 4605.08,4012.65 h36 r45
  text "D15" at 5805.85,4012.19 h36 r45
  text "B13" at 6414.41,4012.3 h36 r45
  text "A12*" at 4904.6,4011.12 h36 r45
  text "GND" at 5400.23,4010.66 h36 r45
  text "VDD" at 2896.86,4009.71 h36 r45
  text "GND" at 3601.07,4009.06 h36 r45
  text "GND" at 4106.32,4009.16 h36 r45
  text "D13" at 6007.56,4006.2 h36 r45
  text "B15*" at 6304.09,4005.99 h36 r45
  text "VDD" at 4700.85,4004.89 h36 r45
  text "VDD" at 5903.02,4000.87 h36 r45
  text "BOOT0" at 3175.54,3982.52 h30 r45
  text "4" at 5220.06,3881.06 h48 r235
  text "8" at 4755.64,3866.36 h48 r270
  text "2" at 5412.72,3866.3 h48 r270
  text "7" at 4919.16,3861.72 h48 r281
  text "13" at 4305.64,3825.36 h48 r90
  text "12" at 4405.64,3825.36 h48 r90
  text "#6" at 5062.66,3820.97 h48 r94
  text "#5" at 5163.66,3820.97 h48 r94
  text "#3" at 5362.66,3819.97 h48 r94
  text "#9" at 4706.64,3818.36 h48 r90
  text "#11" at 4506.93,3797.05 h48 r90
  text "#10" at 4606.29,3790.7 h48 r90
  text "SCL" at 3901.64,3768.36 h48 r90
  text "SDA" at 4001.64,3768.36 h48 r90
  text "GND" at 4202.35,3768.36 h48 r90
  text "TX 1" at 5565.32,3754.14 h48 r90
  text "RX 0" at 5667.63,3753.94 h48 r89
  text "AREF" at 4105.64,3730.36 h48 r90
  text "DIGITAL(#=PWM)" at 4650.13,3728.14 h42
  text "LD:" at 2159.44,3677.01 h36 r270
  text "IDD" at 3044.01,3675.09 h60
  text "USART1" at 5854.41,3613.57 h42
  text "OTG1" at 6264.11,3614.49 h42
  text "AT-Link-EZ V1.2" at 1524.66,3573.01 h60 r270
  text "1" at 2197.62,3560.72 h36 r90
  text "ID" at 6333.52,3550.05 h42 r90
  text "BOOT1" at 2647.25,3542.86 h40
  text "BOOT0" at 2360.02,3541.28 h40
  text "PA10" at 6088.27,3528.26 h42
  text "RX" at 5928.08,3526.3 h42
  text "2" at 2196.62,3493.72 h36 r90
  text "GND" at 2716.59,3455.78 h40
  text "GND" at 2353.72,3454.99 h40
  text "VBUS" at 6264.07,3448.66 h42
  text "PA9" at 6096.56,3446.7 h42
  text "TX" at 5921.96,3440.41 h42
  text "3" at 2195.62,3420.72 h36 r90
  text "4" at 2193.18,3335.13 h36 r54
  text "VDD" at 2718.96,3252.49 h40
  text "VDD" at 2352.54,3251.3 h40
  text "MISO" at 5427.67,3132.03 h42
  text "5V" at 5818.22,3130.05 h42
  text "MOSI" at 5799.72,3029.66 h42
  text "SCK" at 5442.63,3022.97 h42
  text "5V" at 2706.33,2999.91 h42
  text "3V3" at 2302.42,2988.66 h42
  text "NRST" at 5422.55,2929.66 h42
  text "GND" at 5798.54,2923.76 h42
  text "BOOT0" at 2710.08,2892.86 h40
  text "SWD" at 2306.76,2892.38 h42
  text "NSS" at 5444.6,2830.05 h42
  text "PB11" at 5802.47,2825.34 h42
  text "SWO" at 2709.49,2792.47 h42
  text "SWC" at 2301.64,2789.93 h42
  text "OTG1" at 6781.45,2769.95 h56
  text "TX" at 2706.73,2693.36 h42
  text "NRST" at 2300.14,2691.82 h40
  text "GND" at 2309.08,2588.93 h42
  text "RX" at 2709.1,2586.66 h42
  text "AT-Link" at 2419.65,2471.9 h56 r1
  text "AT-START-F435 V1.1" at 4690.14,2377.89 h80
  text "POWER" at 4766.34,2275.2 h42
  text "ANALOG IN" at 5266.34,2275.2 h42
  text "OTG2" at 6772.84,2191.55 h56
  text "AN1" at 5259.83,2156.28 h48 r90
  text "IOREF" at 4367.81,2153.53 h48 r90
  text "AN0" at 5160.54,2153.53 h48 r90
  text "RESET" at 4462.64,2152.36 h48 r90
  text "3.3V" at 4563.64,2151.36 h48 r90
  text "5V" at 4663.64,2151.36 h48 r90
  text "GND" at 4764.64,2151.36 h48 r90
  text "GND" at 4863.93,2151.36 h48 r90
  text "AN2" at 5362.66,2147.22 h48 r90
  text "AN4" at 5566.76,2146.43 h48 r90
  text "AN5" at 5665.65,2146.43 h48 r90
  text "AN3" at 5461.56,2145.24 h48 r90
  text "3V3" at 2007.12,2107.03 h36 r270
  text "SWD" at 1928.72,2105.45 h36 r270
  text "GND" at 1651.34,2103.49 h36 r270
  text "NRST" at 1749.85,2102.3 h36 r270
  text "SWC" at 1839.28,2098.76 h36 r270
  text "RESET" at 2461.61,2090.22 h56
  text "A2" at 4597.35,1928.89 h36 r45
  text "E11" at 6000.98,1928.53 h36 r45
  text "F0" at 3314.02,1927.25 h36 r45
  text "A0" at 4498.95,1926.97 h36 r45
  text "E15" at 6204.91,1926.78 h36 r45
  text "F2" at 3403.08,1926.05 h36 r45
  text "A4" at 4802.53,1926.23 h36 r45
  text "E9" at 5809.92,1926.23 h36 r45
  text "E13" at 6093.6,1926.05 h36 r45
  text "E3" at 2898.31,1925.06 h36 r45
  text "F4" at 3503.13,1924.52 h36 r45
  text "B0" at 5100.11,1924.87 h36 r45
  text "F6" at 3698.67,1923.52 h36 r45
  text "E5" at 3006.98,1922.72 h36 r45
  text "H1*" at 4000.55,1923.06 h36 r45
  text "NC" at 4298.59,1923.28 h36 r45
  text "B2" at 5203.64,1922.52 h36 r45
  text "F12" at 5299.26,1922.65 h36 r45
  text "A6" at 4896.02,1922.24 h36 r45
  text "F14" at 5499.83,1921.97 h36 r45
  text "E7" at 5706.75,1922.35 h36 r45
  text "B11" at 6302.63,1922.47 h36 r45
  text "F8" at 3801.61,1921.06 h36 r45
  text "F10" at 3897.1,1920.92 h36 r45
  text "C2" at 4198.34,1920.98 h36 r45
  text "G0" at 5604.95,1920.32 h36 r45
  text "C0" at 4097.03,1918.06 h36 r45
  text "C4" at 4996.54,1917.98 h36 r45
  text "SWO" at 1842.04,1917.12 h36 r270
  text "BOOT0" at 1934.24,1916.72 h36 r270
  text "VDD" at 5887.96,1917.1 h36 r45
  text "5V" at 2012.25,1915.94 h36 r270
  text "TX" at 1744.89,1914.89 h36 r270
  text "C14*" at 3202.91,1915.43 h36 r45
  text "VDD" at 5387.25,1914.94 h36 r45
  text "VDD" at 6390.51,1915.45 h36 r45
  text "VREF+" at 4352.32,1914.41 h30 r30
  text "GND" at 4694.74,1914.28 h36 r45
  text "RX" at 1650.55,1913.18 h36 r270
  text "VBAT" at 3100.87,1913.46 h36 r45
  text "GND" at 3577.41,1912.47 h36 r30
  text "GND" at 6727.91,1807.33 h36
  text "USER" at 2479.29,1705.97 h56
  text "C1" at 4217.58,1634.73 h36 r45
  text "B1" at 5216.05,1631.68 h36 r45
  text "G1" at 5717.9,1632.21 h36 r45
  text "F5" at 3618.97,1630.12 h36 r45
  text "C3" at 4317.49,1630.32 h36 r45
  text "F1" at 3422.02,1629.07 h36 r45
  text "A1" at 4620.14,1628.84 h36 r45
  text "A5" at 4918.95,1628.09 h36 r45
  text "F3" at 3517.13,1626.81 h36 r45
  text "E2" at 2916.14,1626.2 h36 r45
  text "F9" at 3921.9,1626.08 h36 r45
  text "A3" at 4714.44,1626.16 h36 r45
  text "C5" at 5117.07,1626.24 h36 r45
  text "E8" at 5810.64,1626.23 h36 r45
  text "A7" at 5013.9,1624.67 h36 r45
  text "F11" at 5314.61,1624.75 h36 r45
  text "E6" at 3118.15,1624.15 h36 r45
  text "E4" at 3012.39,1623.35 h36 r45
  text "F7" at 3824.5,1622.32 h36 r45
  text "H0*" at 4007.59,1620.13 h36 r45
  text "E12" at 6114.11,1620.17 h36 r45
  text "H3" at 6418.85,1620.43 h36 r45
  text "F13" at 5515.44,1617.88 h36 r45
  text "F15" at 5613.92,1617.71 h36 r45
  text "E10" at 6018.15,1617.55 h36 r45
  text "B10" at 6312.01,1617.53 h36 r45
  text "E14" at 6219.63,1617.27 h36 r45
  text "C13" at 3207.25,1613.23 h36 r45
  text "GND" at 5399.82,1611.51 h36 r45
  text "GND" at 4400.23,1609.67 h36 r45
  text "VDD" at 3702.59,1609.16 h36 r45
  text "VDD" at 4802.53,1606.07 h36 r45
  text "GND" at 5900.97,1606.46 h36 r45
  text "C15*" at 3299.05,1604.17 h36 r45
  text "1" at 2893.42,1589.61 h36 r180
  text "NRST" at 4100.19,1581.1 h36 r45
  text "VDDA" at 4487.51,1580.21 h36 r45
  text "11" at 3415.75,1571.59 h36 r90
  text "61" at 5897.92,1561.21 h36 r55
  text "21" at 3887.52,1553.56 h36
  text "31" at 4386.33,1553.56 h36
  text "41" at 4882,1553.53 h36
  text "51" at 5377.67,1553.54 h36
  text "71" at 6394.2,1553.59 h36
Bottom Overlay:
  text "143" at 2962.64,4355.99 h36 r45
  text "139" at 3154.64,4354.84 h36 r45
  text "135" at 3370.64,4355.41 h36 r45
  text "133" at 3474.64,4355.41 h36 r45
  text "129" at 3659.97,4354.84 h36 r45
  text "125" at 3862.9,4355.41 h36 r45
  text "123" at 3962.9,4355.41 h36 r45
  text "109" at 4658.97,4354.84 h36 r45
  text "105" at 4867.72,4355.41 h36 r45
  text "103" at 4960.49,4355.41 h36 r45
  text "141" at 3053.31,4353.1 h36 r45
  text "131" at 3567.97,4352.52 h36 r45
  text "121" at 4060.23,4352.52 h36 r45
  text "101" at 5044.82,4352.52 h36 r45
  text "137" at 3263.97,4351.94 h36 r45
  text "127" at 3757.31,4351.94 h36 r45
  text "107" at 4760.72,4351.94 h36 r45
  text "119" at 4156.23,4349.63 h36 r45
  text "115" at 4357.57,4350.21 h36 r45
  text "113" at 4461.97,4350.21 h36 r45
  text "99" at 5146.34,4347.55 h36 r45
  text "95" at 5348.2,4348.12 h36 r45
  text "93" at 5450.34,4348.12 h36 r45
  text "89" at 5647.39,4347.55 h36 r45
  text "85" at 5843.84,4348.12 h36 r45
  text "83" at 5951.25,4348.12 h36 r45
  text "117" at 4257.57,4346.74 h36 r45
  text "111" at 4549.97,4347.31 h36 r45
  text "79" at 6147.38,4345.81 h36 r45
  text "75" at 6349.3,4346.39 h36 r45
  text "73" at 6449.01,4346.39 h36 r45
  text "97" at 5242.34,4344.65 h36 r45
  text "91" at 5541.25,4345.23 h36 r45
  text "87" at 5745.77,4344.65 h36 r45
  text "81" at 6048.1,4345.23 h36 r45
  text "77" at 6247.58,4342.92 h36 r45
  text "142" at 3057.31,4079.64 h36 r45
  text "132" at 3561.31,4079.06 h36 r45
  text "122" at 4050.9,4079.06 h36 r45
  text "102" at 5062.92,4079.06 h36 r45
  text "144" at 2952.56,4077.33 h36 r45
  text "140" at 3158.64,4077.33 h36 r45
  text "138" at 3259.97,4077.33 h36 r45
  text "134" at 3463.97,4076.75 h36 r45
  text "130" at 3653.31,4076.75 h36 r45
  text "128" at 3758.64,4077.33 h36 r45
  text "124" at 3956.23,4076.75 h36 r45
  text "120" at 4162.9,4076.75 h36 r45
  text "108" at 4757.97,4077.33 h36 r45
  text "104" at 4956.16,4076.75 h36 r45
  text "100" at 5157.49,4076.75 h36 r45
  text "136" at 3367.97,4076.17 h36 r45
  text "126" at 3858.9,4076.17 h36 r45
  text "106" at 4847.72,4076.17 h36 r45
  text "112" at 4549.64,4073.86 h36 r45
  text "118" at 4254.9,4072.12 h36 r45
  text "114" at 4449.64,4071.54 h36 r45
  text "110" at 4649.97,4071.54 h36 r45
  text "92" at 5547.06,4071.77 h36 r45
  text "82" at 6051.01,4071.77 h36 r45
  text "116" at 4346.9,4070.96 h36 r45
  text "98" at 5253.16,4070.04 h36 r45
  text "88" at 5754.82,4070.04 h36 r45
  text "96" at 5351.82,4068.88 h36 r45
  text "94" at 5450.49,4069.46 h36 r45
  text "90" at 5653.39,4069.46 h36 r45
  text "86" at 5848.73,4068.88 h36 r45
  text "84" at 5950.39,4069.46 h36 r45
  text "80" at 6152.97,4069.46 h36 r45
  text "78" at 6253.59,4068.3 h36 r45
  text "74" at 6455.73,4067.72 h36 r45
  text "76" at 6355.16,4067.14 h36 r45
  text "VDD" at 2028.09,3148.57 h36 r270
  text "GND" at 2056.09,2286.57 h36
  text "AT32F435ZMT7" at 5102.51,2139.53 h120
  text "42" at 4954.55,1952.93 h36 r45
  text "40" at 4856.32,1950.61 h36 r45
  text "44" at 5051.7,1950.62 h36 r45
  text "48" at 5255.27,1951.19 h36 r45
  text "46" at 5155.27,1950.04 h36 r45
  text "22" at 3950.66,1948.88 h36 r45
  text "4" at 3040.75,1948.03 h36 r81
  text "32" at 4450.06,1947.72 h36 r45
  text "52" at 5451.98,1947.72 h36 r45
  text "62" at 5953.32,1948.3 h36 r45
  text "20" at 3848.3,1946.57 h36 r45
  text "24" at 4051.45,1946.56 h36 r45
  text "28" at 4251.14,1947.14 h36 r45
  text "68" at 6248.65,1946.56 h36 r45
  text "72" at 6449.65,1946.57 h36 r45
  text "26" at 4148.28,1945.99 h36 r45
  text "38" at 4754.89,1945.99 h36 r45
  text "58" at 5753.32,1945.99 h36 r45
  text "60" at 5852.32,1945.99 h36 r45
  text "64" at 6049.65,1945.99 h36 r45
  text "30" at 4352.2,1945.41 h36 r45
  text "34" at 4552.91,1945.41 h36 r45
  text "36" at 4652.03,1944.83 h36 r45
  text "50" at 5351.55,1945.41 h36 r45
  text "54" at 5554.98,1945.41 h36 r45
  text "56" at 5652.98,1944.83 h36 r45
  text "66" at 6148.65,1945.41 h36 r45
  text "12" at 3442.79,1943.67 h36 r45
  text "70" at 6349.65,1944.25 h36 r45
  text "18" at 3745.54,1941.94 h36 r45
  text "10" at 3342.39,1941.36 h36 r45
  text "14" at 3542,1941.36 h36 r45
  text "16" at 3640.42,1940.78 h36 r45
  text "2" at 2934.52,1936.96 h36 r45
  text "8" at 3236.88,1934.65 h36 r45
  text "6" at 3132.76,1932.23 h36 r36
  text "43" at 5052.93,1678.06 h36 r45
  text "45" at 5150.07,1678.06 h36 r45
  text "49" at 5353.5,1677.48 h36 r45
  text "41" at 4947.21,1675.17 h36 r45
  text "47" at 5252.93,1674.59 h36 r45
  text "23" at 4051.79,1674.01 h36 r45
  text "25" at 4150.94,1674.01 h36 r45
  text "29" at 4348.43,1673.43 h36 r45
  text "33" at 4549.15,1672.85 h36 r45
  text "35" at 4650.98,1672.85 h36 r45
  text "53" at 5553.64,1672.85 h36 r45
  text "55" at 5649.64,1672.85 h36 r45
  text "63" at 6051.31,1673.43 h36 r45
  text "65" at 6158.31,1673.43 h36 r45
  text "69" at 6351.31,1672.85 h36 r45
  text "39" at 4853.98,1672.27 h36 r45
  text "59" at 5850.98,1672.27 h36 r45
  text "21" at 3945.57,1671.12 h36 r45
  text "27" at 4254.51,1670.54 h36 r45
  text "61" at 5947.98,1670.54 h36 r45
  text "31" at 4445.57,1669.96 h36 r45
  text "51" at 5443.64,1669.96 h36 r45
  text "67" at 6254.31,1669.96 h36 r45
  text "13" at 3543.2,1668.8 h36 r45
  text "15" at 3650.55,1668.8 h36 r45
  text "37" at 4749.69,1669.38 h36 r45
  text "57" at 5749.98,1669.38 h36 r45
  text "71" at 6446.31,1668.8 h36 r45
  text "19" at 3843.67,1668.23 h36 r45
  text "11" at 3415.38,1665.91 h36 r315
  text "17" at 3746.7,1665.33 h36 r45
  text "7" at 3241.09,1662.88 h36 r70
  text "3" at 3038.87,1660.94 h36 r45
  text "5" at 3136.12,1660.94 h36 r45
  text "9" at 3332.99,1660.45 h36 r40
  text "1" at 2928.64,1659.2 h36 r45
